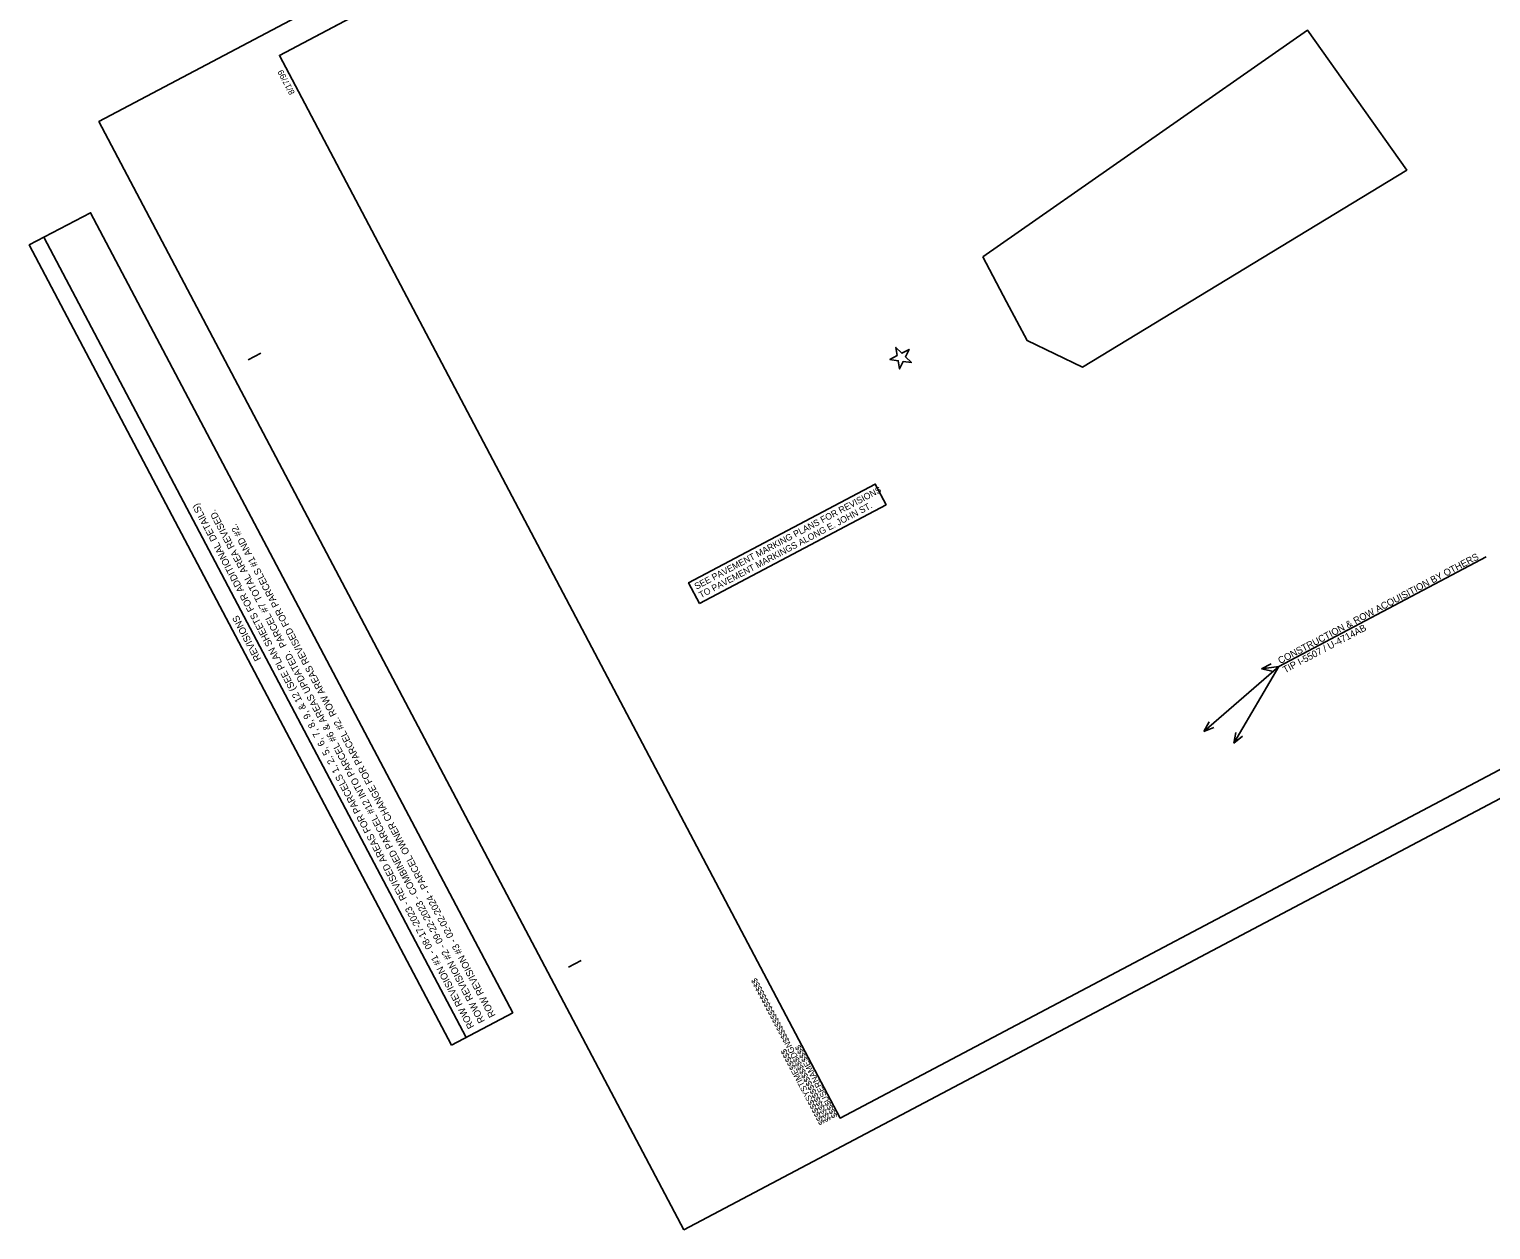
# Model space of a CAD drawing. Extents: x 1486990 to 1489232, y 497582 to 499336.
# Drawn here: x 1486990 to 1488268, y 497582 to 498631 of the extents above; entities that cross this region are included whole.
import ezdxf

# ---------------------------------------------------------------- set-up
doc = ezdxf.new("R2010")
doc.units = 0
for name, color, linetype in [('PROF-MAJR-LABL', 7, 'Continuous'), ('Prop Drainage Ditch Boundaries', 7, 'Continuous'), ('Prop Drainage Structure Catch Basin Adjust CELL', 7, 'Continuous'), ('Prop Drainage Structure Catch Basin Open Throat 1 CELL', 7, 'Continuous'), ('Prop Drainage Structure Pipe Alternate 15in', 7, 'Continuous'), ('Prop Drainage Structure Pipe Outlet Channel Detail CELL', 7, 'Continuous'), ('Prop Drainage Structure Plot Symbol 20 Scale', 7, 'Continuous'), ('Prop Earthen Structure V Ditch Berm Detail CELL', 7, 'Continuous')]:
    doc.layers.add(name, color=color, linetype=linetype)

msp = doc.modelspace()

# ---------------------------------------------------------------- linework, layer by layer
at = {"layer": 'PROF-MAJR-LABL'}
msp.add_lwpolyline([(1487748.8, 498345.8), (1487742.4, 498342.4), (1487749.6, 498341.4), (1487750.8, 498334.2), (1487754, 498340.7), (1487761.2, 498339.7), (1487756, 498344.8), (1487759.2, 498351.3), (1487752.8, 498347.9), (1487747.6, 498353), (1487748.8, 498345.8)], dxfattribs=at)
at = {"layer": 'Prop Drainage Ditch Boundaries'}
msp.add_lwpolyline([(1487562.2, 497582), (1489050.9, 498368), (1488539.7, 499336.3), (1487050.9, 498550.3)], close=True, dxfattribs=at)
at = {"layer": 'Prop Drainage Structure Catch Basin Adjust CELL'}
msp.add_line((1487372, 497750.1), (1487002.8, 498449.2), dxfattribs=at)
msp.add_lwpolyline([(1487359.1, 497743.3), (1486989.9, 498442.5), (1487043.5, 498470.7), (1487412.6, 497771.6)], close=True, dxfattribs=at)
at = {"layer": 'Prop Drainage Structure Catch Basin Open Throat 1 CELL'}
for p, q in [((1487208.7, 498608.1), (1487208.7, 498608.1)), ((1487181.3, 498342), (1487192.3, 498347.9)), ((1487461.4, 497811.4), (1487472.5, 497817.3)), ((1487698.9, 497679.6), (1487698.9, 497679.6))]:
    msp.add_line(p, q, dxfattribs=at)
for points in [[(1488535.1, 499308.5), (1487208.7, 498608.1), (1487698.9, 497679.6), (1489025.4, 498380)], [(1487698.9, 497679.6), (1487208.7, 498608.1), (1488358.2, 499215.1), (1488428.3, 499082.4), (1488605.2, 499175.8), (1489025.4, 498380)]]:
    msp.add_lwpolyline(points, close=True, dxfattribs=at)
at = {"layer": 'Prop Drainage Structure Pipe Outlet Channel Detail CELL'}
for p, q in [((1488082.4, 498074.2), (1488263.6, 498169.9)), ((1488082.4, 498074.2), (1488016.7, 498017.4)), ((1488082.4, 498074.2), (1488043.1, 498007.2)), ((1488075.8, 498076.6), (1488067.3, 498072.2)), ((1488082.4, 498074.2), (1488067.3, 498072.2)), ((1488076.7, 498070.1), (1488067.3, 498072.2)), ((1488021.4, 498025.7), (1488016.7, 498017.4)), ((1488025.7, 498020.8), (1488016.7, 498017.4)), ((1488044.9, 498016.6), (1488043.1, 498007.2)), ((1488050.5, 498013.3), (1488043.1, 498007.2))]:
    msp.add_line(p, q, dxfattribs=at)
at = {"layer": 'Prop Drainage Structure Plot Symbol 20 Scale'}
for points in [[(1487208.7, 498608.1), (1488222.1, 499143.2), (1488965.4, 498493.7), (1489025.4, 498380), (1487699, 497679.6)], [(1487823.6, 498432.2), (1487844.4, 498392.9), (1487862.4, 498358.9), (1487910.8, 498335.8), (1488194.2, 498508), (1488107.4, 498630.3)]]:
    msp.add_lwpolyline(points, close=True, dxfattribs=at)
at = {"layer": 'Prop Earthen Structure V Ditch Berm Detail CELL'}
msp.add_lwpolyline([(1487575.9, 498129.3), (1487739.1, 498215.5), (1487729.6, 498233.5), (1487566.4, 498147.3)], close=True, dxfattribs=at)

# ---------------------------------------------------------------- texts
for s, p in [('$$$$$$$$$$$$$$$$DGN$$$$$$$$$$$$$$$$', (1487691.1, 497678.1)), ('$$$$$$SYSTIME$$$$$', (1487685.7, 497675.3)), ('$$$$USERNAME$$$$', (1487696.9, 497681.2))]:
    msp.add_text(s, height=5.25, rotation=117.8351).set_placement(p)
at = {"layer": 'Prop Drainage Structure Catch Basin Adjust CELL'}
for s, p in [('ROW REVISION #1 - 08-17-2023 - REVISED AREAS FOR PARCELS 1, 2, 5, 6, 7, 8, 9, & 12 (SEE PLAN SHEETS FOR ADDITIONAL DETAILS)', (1487379.2, 497759.5)), ('ROW REVISION #2 - 09-22-2023 - COMBINED PARCEL #12 INTO PARCEL #6 & AREAS UPDATED.  PARCEL #7 TOTAL AREA REVISED.', (1487388.5, 497764.4)), ('ROW REVISION #3 - 02-02-2024 - PARCEL OWNER CHANGE FOR PARCEL #2. ROW AREAS REVISED FOR PARCELS #1 AND #2.', (1487397.8, 497769.3)), ('REVISIONS', (1487192.8, 498080.8))]:
    msp.add_text(s, height=6, rotation=117.8351, dxfattribs=at).set_placement(p)
at = {"layer": 'Prop Drainage Structure Catch Basin Open Throat 1 CELL'}
msp.add_text('8/17/99', height=5.25, rotation=117.8351, dxfattribs=at).set_placement((1487222.3, 498575.5))
at = {"layer": 'Prop Drainage Structure Pipe Alternate 15in'}
for s, p in [('SEE PAVEMENT MARKING PLANS FOR REVISIONS', (1487573.3, 498141.2)), ('TO PAVEMENT MARKINGS ALONG E. JOHN ST.', (1487577.2, 498133.7))]:
    msp.add_text(s, height=5.625, rotation=27.8351, dxfattribs=at).set_placement(p)
at = {"layer": 'Prop Drainage Structure Pipe Outlet Channel Detail CELL'}
for s, p in [('CONSTRUCTION & ROW ACQUISITION BY OTHERS', (1488083.6, 498076.2)), ('TIP I-5507 / U-4714AB', (1488087.8, 498068.2))]:
    msp.add_text(s, height=6, rotation=27.8351, dxfattribs=at).set_placement(p)

doc.saveas('drawing.dxf')
